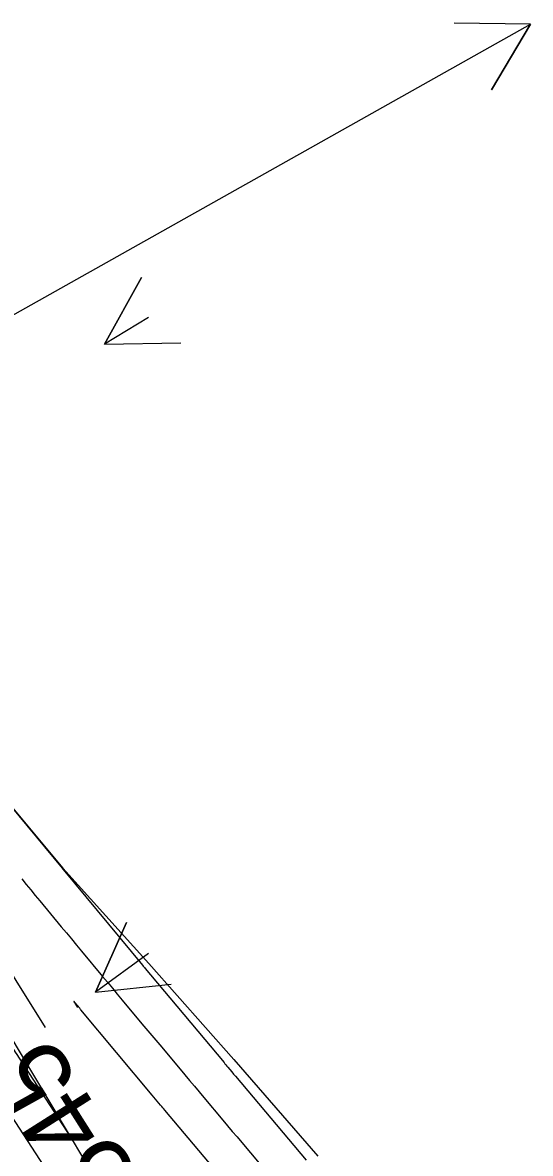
# Model space of a CAD drawing. Extents: x 954385 to 988206, y 1868364 to 1924553.
# Drawn here: x 957697.2 to 957737.1, y 1920153.2 to 1920242.1 of the extents above; entities that cross this region are included whole.
import ezdxf

# ---------------------------------------------------------------- set-up
doc = ezdxf.new("R2010")
doc.units = 0
for name, color, linetype in [('1', 7, 'Continuous'), ('Ex_Contour Labels', 7, 'Continuous'), ('Ex_Major Contours', 7, 'Continuous'), ('Ex_Minor Contours', 7, 'Continuous'), ('Perimeter', 7, 'Continuous'), ('Slopes', 7, 'Continuous')]:
    doc.layers.add(name, color=color, linetype=linetype)

msp = doc.modelspace()

# ---------------------------------------------------------------- linework, layer by layer
at = {"layer": '1'}
for points in [[(957642.475, 1920245.119), (957647.904, 1920236.718), (957650.092, 1920233.249), (957653.344, 1920228.325), (957658.665, 1920219.852), (957664.238, 1920211.548), (957669.658, 1920203.141), (957675.294, 1920194.881), (957680.805, 1920186.536), (957686.502, 1920178.317), (957690.062, 1920172.865), (957691.817, 1920169.839), (957696.948, 1920161.236), (957702.103, 1920152.651)], [(957672.968, 1920198.29), (957674.612, 1920195.665), (957674.887, 1920195.228), (957675.161, 1920194.791), (957675.436, 1920194.354), (957675.712, 1920193.918), (957680.487, 1920186.357), (957680.511, 1920186.319), (957680.586, 1920186.201), (957685.024, 1920179.228), (957685.449, 1920178.56), (957685.875, 1920177.893), (957686.302, 1920177.225), (957686.729, 1920176.558), (957689.363, 1920172.446), (957689.399, 1920172.39), (957689.411, 1920172.371), (957691.265, 1920169.489), (957691.286, 1920169.456), (957696.692, 1920161.094), (957696.719, 1920161.052), (957701.051, 1920154.402)], [(957699.54, 1920151.226), (957694.374, 1920159.155)]]:
    msp.add_lwpolyline(points, dxfattribs=at)
at = {"layer": 'Ex_Major Contours'}
msp.add_lwpolyline([(957696.171, 1920180.679), (957700.334, 1920175.626), (957700.361, 1920175.593), (957700.415, 1920175.529), (957706.66, 1920168.003), (957706.712, 1920167.94), (957706.765, 1920167.877), (957706.818, 1920167.814), (957706.87, 1920167.751), (957707.292, 1920167.247), (957713.061, 1920160.344), (957713.136, 1920160.254), (957713.211, 1920160.165), (957713.287, 1920160.075), (957713.362, 1920159.986), (957713.663, 1920159.628), (957713.814, 1920159.449), (957713.964, 1920159.27), (957719.523, 1920152.665)], dxfattribs=at)
at = {"layer": 'Ex_Minor Contours'}
for points in [[(957697.151, 1920174.794), (957697.508, 1920174.362), (957697.864, 1920173.929), (957698.222, 1920173.498), (957698.579, 1920173.066), (957700.264, 1920171.034), (957700.665, 1920170.552), (957701.065, 1920170.07), (957701.465, 1920169.587), (957701.865, 1920169.105), (957703.506, 1920167.127), (957703.893, 1920166.662), (957704.28, 1920166.196), (957704.668, 1920165.731), (957705.056, 1920165.267), (957706.609, 1920163.408), (957707.386, 1920162.479), (957708.162, 1920161.55), (957709.983, 1920159.372), (957710.355, 1920158.928), (957710.727, 1920158.484), (957711.099, 1920158.041), (957711.472, 1920157.598), (957712.963, 1920155.826), (957713.336, 1920155.383), (957713.709, 1920154.94), (957714.082, 1920154.497), (957714.455, 1920154.054), (957716.497, 1920151.627)], [(957699.025, 1920163.094), (957694.387, 1920170.491)], [(957713.327, 1920150.761), (957708.405, 1920156.607), (957708.323, 1920156.705), (957708.241, 1920156.802), (957708.159, 1920156.9), (957708.077, 1920156.998), (957707.422, 1920157.782), (957701.811, 1920164.494), (957701.778, 1920164.534), (957701.712, 1920164.614), (957701.323, 1920165.083), (957701.27, 1920165.143), (957701.249, 1920165.16), (957701.259, 1920165.135), (957701.3, 1920165.066), (957701.538, 1920164.686)]]:
    msp.add_lwpolyline(points, dxfattribs=at)
at = {"layer": 'Perimeter'}
msp.add_lwpolyline([(957645.505, 1920247.168), (957651.24, 1920238.975), (957657.104, 1920230.868), (957663.303, 1920222.989), (957669.266, 1920214.949), (957671.938, 1920211.601), (957675.531, 1920207.114), (957681.545, 1920199.11), (957687.849, 1920191.301), (957693.938, 1920183.347), (957700.39, 1920175.638), (957707.155, 1920168.141), (957713.84, 1920160.59), (957720.434, 1920152.977)], dxfattribs=at)
at = {"layer": 'Slopes'}
for points in [[(957607.131, 1920168.928), (957737.148, 1920242.007), (957734.089, 1920236.845), (957737.148, 1920242.007), (957731.149, 1920242.076)], [(957707.131, 1920218.928), (957703.657, 1920216.842), (957706.568, 1920222.089), (957703.657, 1920216.842), (957709.656, 1920216.945)], [(957707.131, 1920168.928), (957702.945, 1920165.894), (957705.392, 1920171.373), (957702.945, 1920165.894), (957708.913, 1920166.515)]]:
    msp.add_lwpolyline(points, dxfattribs=at)

# ---------------------------------------------------------------- texts
at = {"layer": 'Ex_Contour Labels'}
msp.add_text('545', height=6, rotation=122.35719, dxfattribs=at).set_placement((957706.501, 1920151.342))

doc.saveas('drawing.dxf')
